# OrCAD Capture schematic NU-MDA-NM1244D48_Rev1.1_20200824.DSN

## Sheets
1 Connect: size A4; title: Nu-MDA-NM1244D48_Connect; rev: V1.0
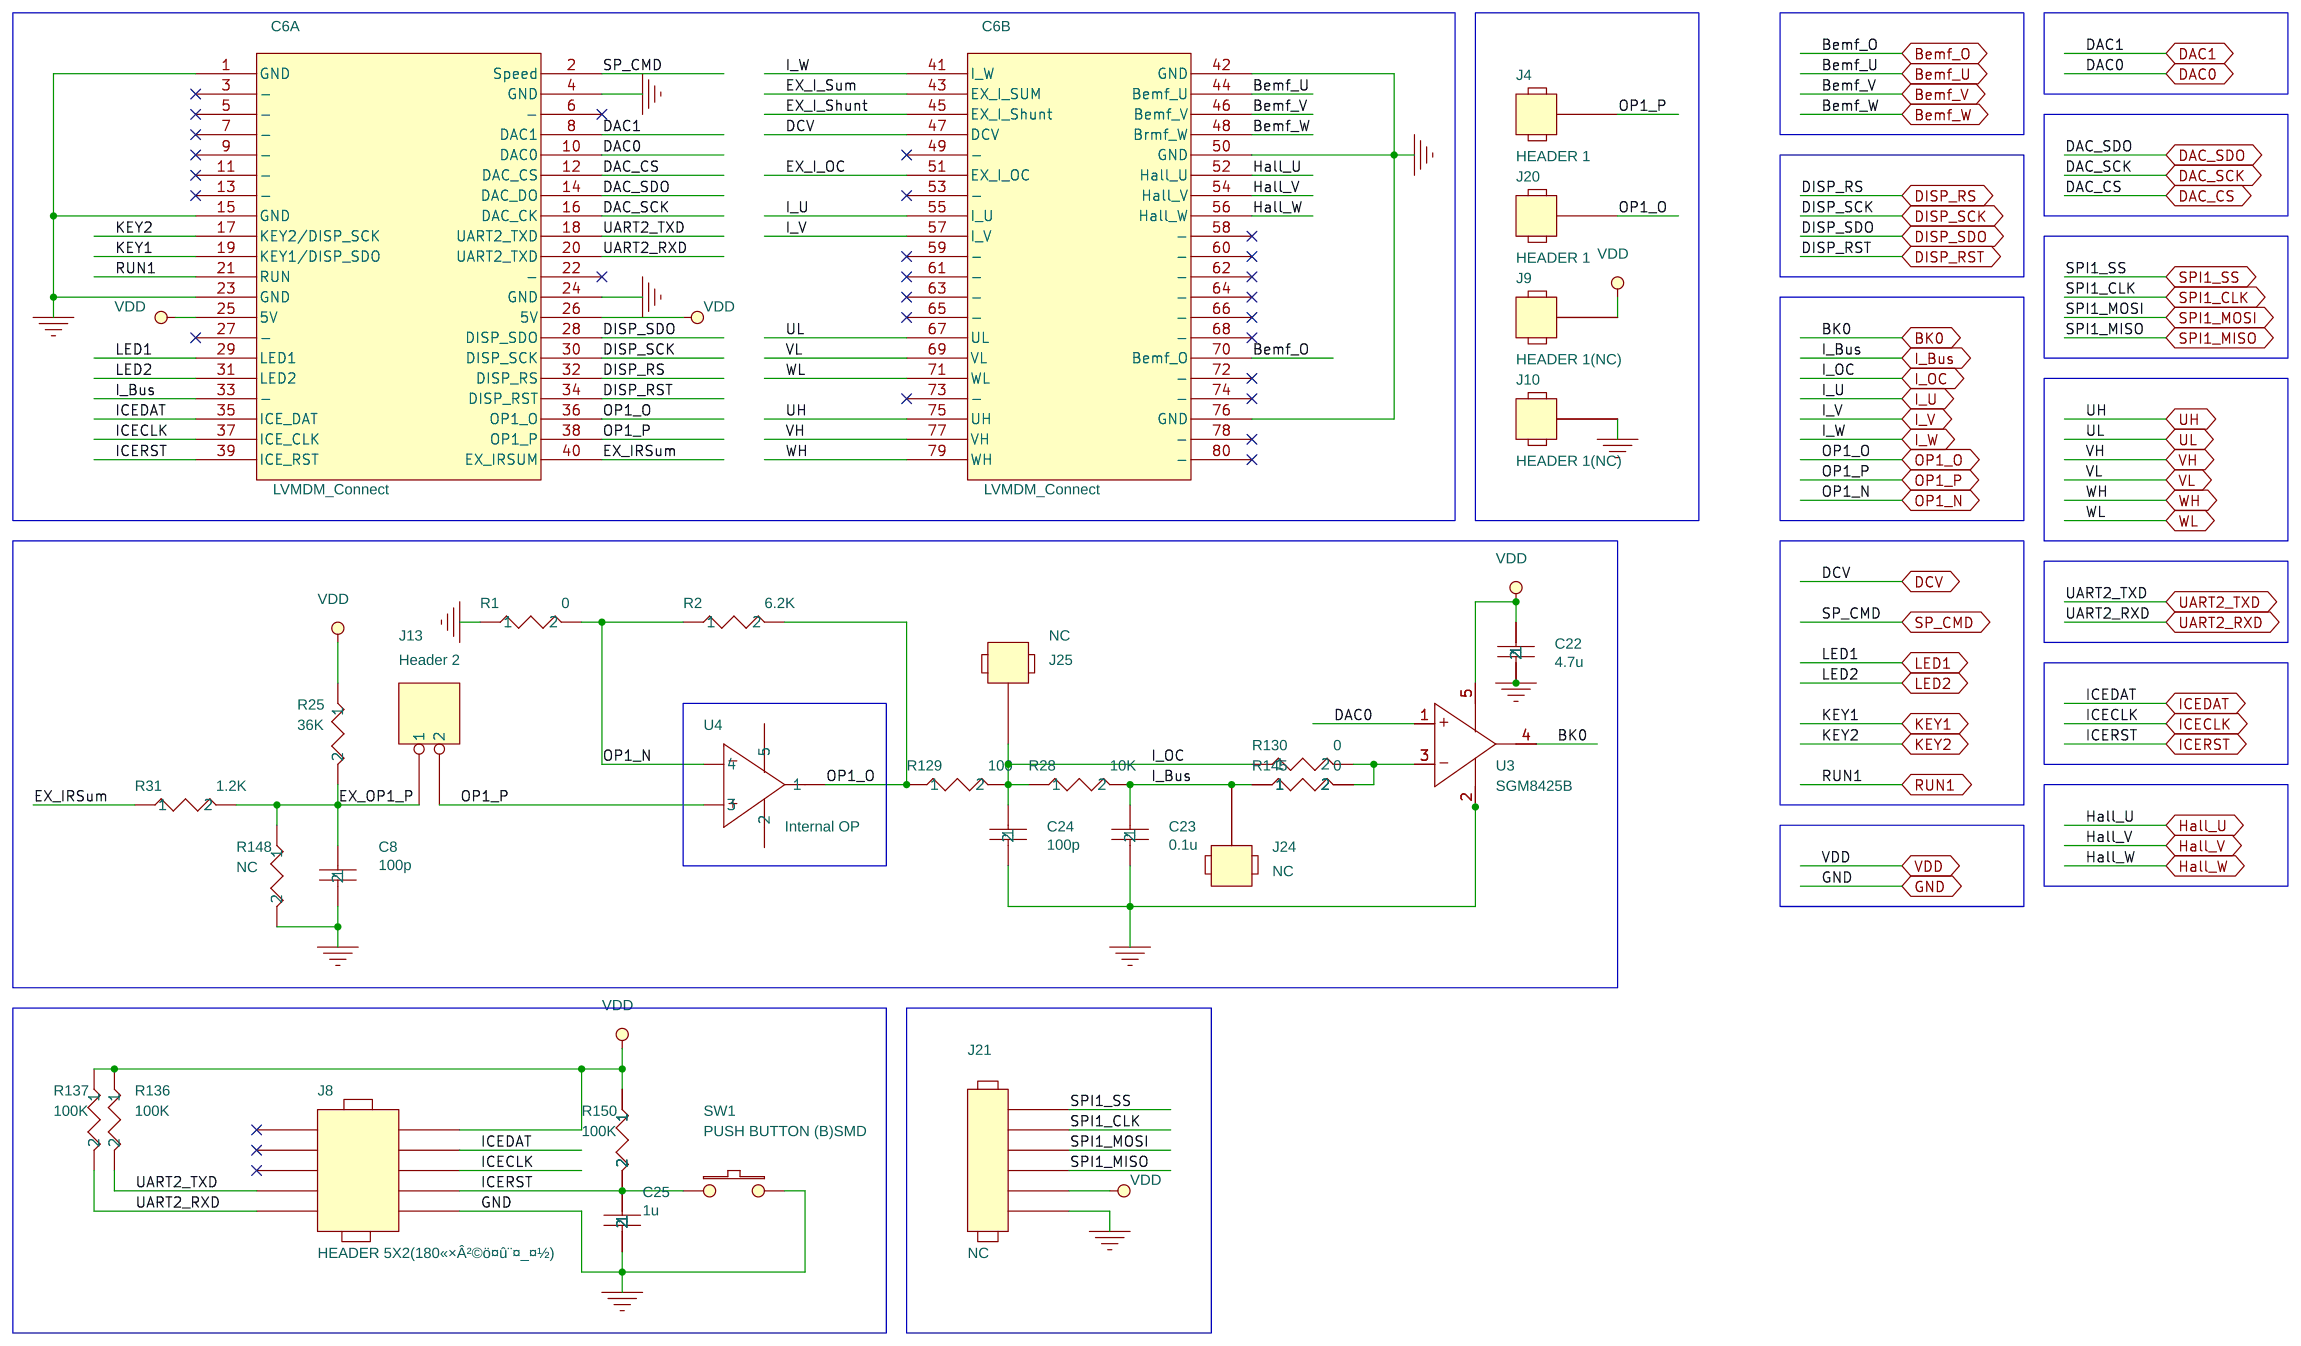
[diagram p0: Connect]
2 NM1244D48: size A3; title: Nu-MDA-NM1244D48
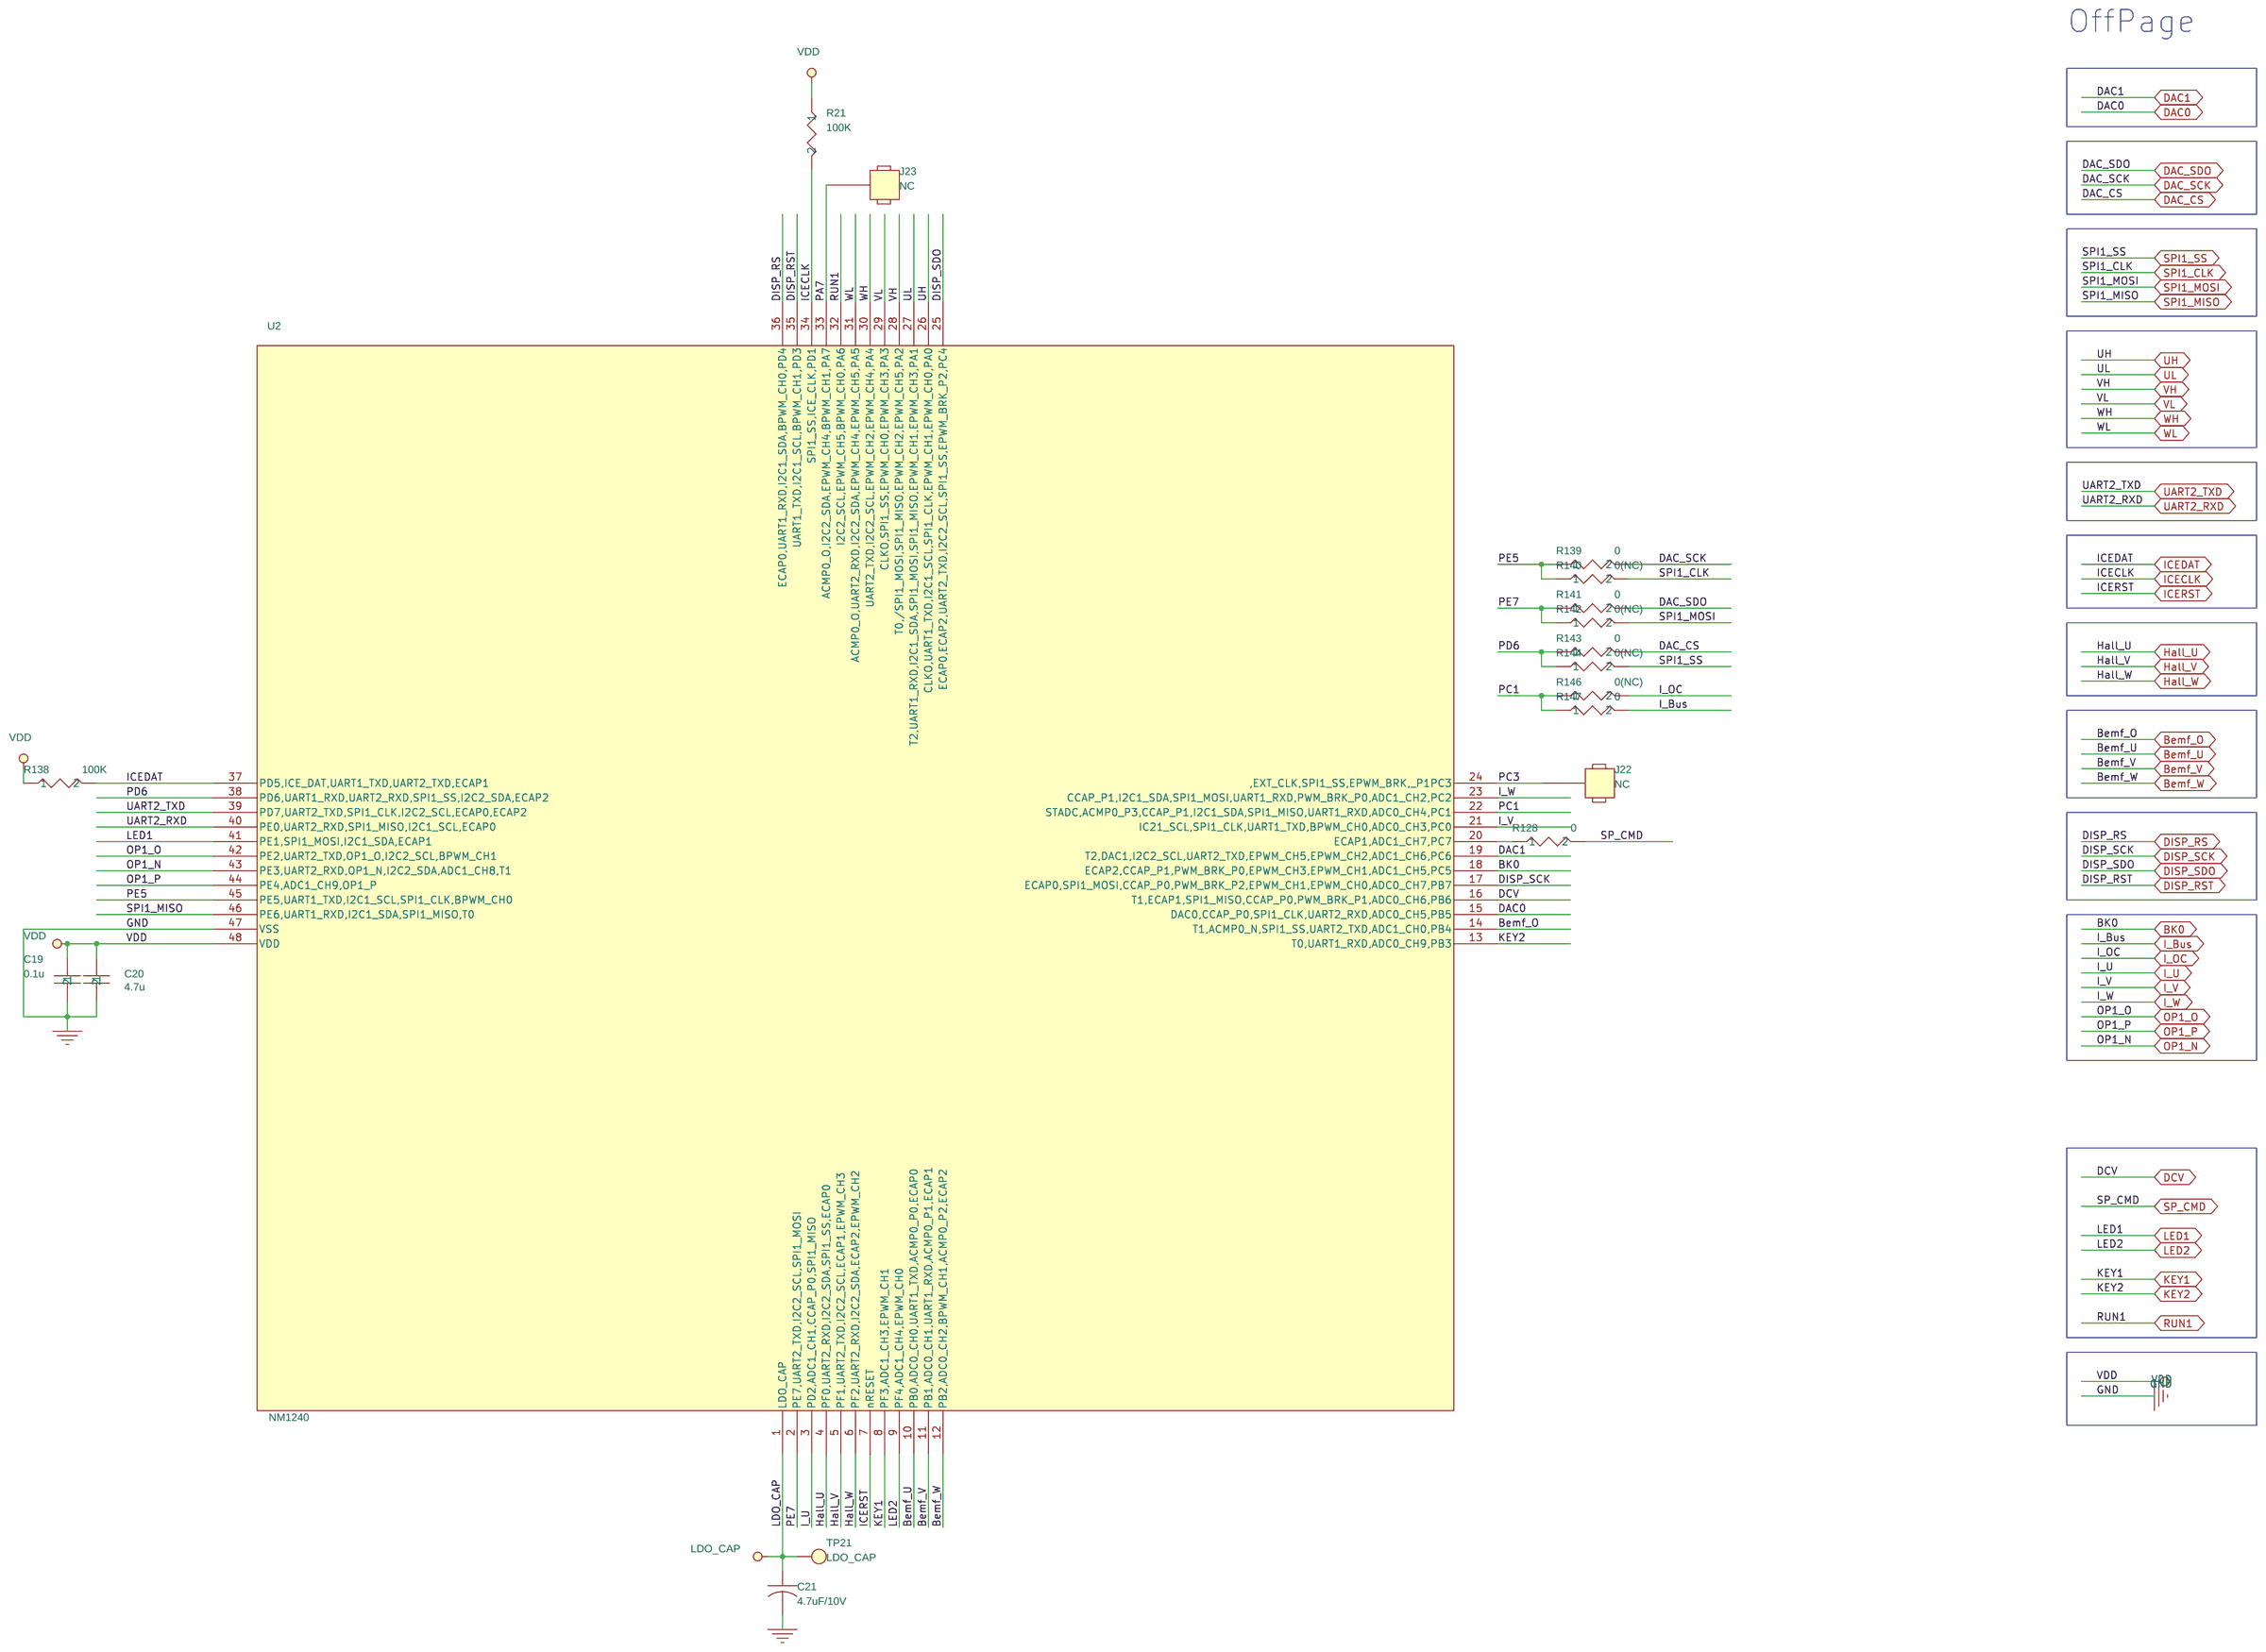
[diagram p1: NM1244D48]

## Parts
sheet Connect
C6  LVMDM_Connect  (sections A,B)
C8  100p  [C0603]
C22  4.7u  [C0603]
C23  0.1u  [C0603]
C24  100p  [C0603]
C25  1u  [C0603]
J4  HEADER 1  [sip-1p]
J8  HEADER 5X2(180«×Â²©ö¤û¨¤_¤½)  [header2x5]
J9  HEADER 1(NC)  [sip-1p]
J10  HEADER 1(NC)  [sip-1p]
J13  Header 2  [SIP-2P]
J20  HEADER 1  [sip-1p]
J21  NC
J24  NC  [sip-1p]
J25  NC  [sip-1p]
R1  0  [R0603]
R2  6.2K  [R0603]
R25  36K  [R0603]
R28  10K  [R0603]
R31  1.2K  [R0603]
R129  100  [R0603]
R130  0  [R0603]
R136  100K  [R0603]
R137  100K  [R0603]
R145  0  [R0603]
R148  NC  [R0603]
R150  100K  [R0603]
SW1  PUSH BUTTON (B)SMD  [SW_SMD_HSM]
U3  SGM8425B  [SOT-23-5]
U4  Internal OP
sheet NM1244D48
C19  0.1u  [C0603]
C20  4.7u  [C0603]
C21  4.7uF/10V  [TANT-A]
J22  NC  [sip-1p]
J23  NC  [sip-1p]
R21  100K  [R0603]
R128  0  [R0603]
R138  100K  [R0603]
R139  0  [R0603]
R140  0(NC)  [R0603]
R141  0  [R0603]
R142  0(NC)  [R0603]
R143  0  [R0603]
R144  0(NC)  [R0603]
R146  0(NC)  [R0603]
R147  0  [R0603]
TP21  LDO_CAP  [TEST_POINT_2MM_SMD]
U2  NM1240  [LQFP-48]

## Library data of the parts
C6 = LVMDM_Connect_7
C8 = C_1u_1
C22 = C_1u_3
C20 C23 = C_1u
C24 = C_1u_2
C25 = C_1u_4
J4 J9 J10 J20 J22-J25 = HEADER_1
J8 = HEADER_5X2
J13 = Header_0_ohm
J21 = HEADER_6
R1 R146 = R_1K_2
R2 R147 = R_1K_1
R25 = R_10K_1
R28 R128 = R_1K
R31 R144 = R_1K_5
R129 R140 = R_1K_3
R130 R139 = R_1K_6
R136 = R_10K_3
R137 = R_10K_4
R142 R145 = R_1K_4
R148 = R_10K
R150 = R_10K_2
SW1 = PUSH_BOTTOM_(B)
U3 = SGM8425B
U4 = SGM8631
C19 = C_0.1u
C21 = C_1uF_16V
R21 = R_100K_1
R138 = R_100K
R141 = R_1K_7
R143 = R_1K_8
TP21 = T_POINT_R
U2 = TF5103_3

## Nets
GND: C6.1(GND) C6.4(GND) C6.15(GND) C6.23(GND) C6.24(GND) C6.42(GND) C6.50(GND) C6.76(GND) C8.2 C19.2 C20.2 C21.2 C22.2 C23.2 C24.2 C25.2 J8.10 J10.1 J21.6 R1.1 R148.2 SW1.2 U2.47(VSS) U3.2
VDD: C6.25(5V) C6.26(5V) C19.1 C20.1 C22.1 J8.2 J9.1 J21.5 R21.1 R25.1 R136.1 R137.1 R138.1 R150.1 U2.48(VDD) U3.5
Bemf_O: C6.70(Bemf_O) U2.14(T1,ACMP0_N,SPI1_SS,UART2_TXD,ADC1_CH0,PB4)
Bemf_U: C6.44(Bemf_U) U2.10(PB0,ADC0_CH0,UART1_TXD,ACMP0_P0,ECAP0)
Bemf_V: C6.46(Bemf_V) U2.11(PB1,ADC0_CH1,UART1_RXD,ACMP0_P1,ECAP1)
Bemf_W: C6.48(Brmf_W) U2.12(PB2,ADC0_CH2,BPWM_CH1,ACMP0_P2,ECAP2)
BK0: U2.18(ECAP2,CCAP_P1,PWM_BRK_P0,EPWM_CH3,EPWM_CH1,ADC1_CH5,PC5) U3.4
DAC0: C6.10(DAC0) U2.15(DAC0,CCAP_P0,SPI1_CLK,UART2_RXD,ADC0_CH5,PB5) U3.1
DAC1: C6.8(DAC1) U2.19(T2,DAC1,I2C2_SCL,UART2_TXD,EPWM_CH5,EPWM_CH2,ADC1_CH6,PC6)
DAC_CS: C6.12(DAC_CS) R143.2
DAC_SCK: C6.16(DAC_CK) R139.2
DAC_SDO: C6.14(DAC_DO) R141.2
DCV: C6.47(DCV) U2.16(T1,ECAP1,SPI1_MISO,CCAP_P0,PWM_BRK_P1,ADC0_CH6,PB6)
DISP_RS: C6.32(DISP_RS) U2.36(ECAP0,UART1_RXD,I2C1_SDA,BPWM_CH0,PD4)
DISP_RST: C6.34(DISP_RST) U2.35(UART1_TXD,I2C1_SCL,BPWM_CH1,PD3)
DISP_SCK: C6.30(DISP_SCK) U2.17(ECAP0,SPI1_MOSI,CCAP_P0,PWM_BRK_P2,EPWM_CH1,EPWM_CH0,ADC0_CH7,PB7)
DISP_SDO: C6.28(DISP_SDO) U2.25(ECAP0,ECAP2,UART2_TXD,I2C2_SCL,SPI1_SS,EPWM_BRK_P2,PC4)
EX_I_OC: C6.51(EX_I_OC)
EX_I_Shunt: C6.45(EX_I_Shunt)
EX_I_Sum: C6.43(EX_I_SUM)
EX_IRSum: C6.40(EX_IRSUM) R31.1
EX_OP1_P: C8.1 J13.1 R25.2 R31.2 R148.1
Hall_U: C6.52(Hall_U) U2.4(PF0,UART2_RXD,I2C2_SDA,SPI1_SS,ECAP0)
Hall_V: C6.54(Hall_V) U2.5(PF1,UART2_TXD,I2C2_SCL,ECAP1,EPWM_CH3)
Hall_W: C6.56(Hall_W) U2.6(PF2,UART2_RXD,I2C2_SDA,ECAP2,EPWM_CH2)
I_Bus: C6.33(-) C23.1 J24.1 R28.2 R145.1 R147.2
I_OC: C24.1 J25.1 R28.1 R129.2 R130.1 R146.2
I_U: C6.55(I_U) U2.3(PD2,ADC1_CH1,CCAP_P0,SPI1_MISO)
I_V: C6.57(I_V) U2.21(IC21_SCL,SPI1_CLK,UART1_TXD,BPWM_CH0,ADC0_CH3,PC0)
I_W: C6.41(I_W) U2.23(CCAP_P1,I2C1_SDA,SPI1_MOSI,UART1_RXD,PWM_BRK_P0,ADC1_CH2,PC2)
ICECLK: C6.37(ICE_CLK) J8.6 R21.2 U2.34(SPI1_SS,ICE_CLK,PD1)
ICEDAT: C6.35(ICE_DAT) J8.4 R138.2 U2.37(PD5,ICE_DAT,UART1_TXD,UART2_TXD,ECAP1)
ICERST: C6.39(ICE_RST) C25.1 J8.8 R150.2 SW1.1 U2.7(nRESET)
KEY1: C6.19(KEY1/DISP_SDO) U2.8(PF3,ADC1_CH3,EPWM_CH1)
KEY2: C6.17(KEY2/DISP_SCK) U2.13(T0,UART1_RXD,ADC0_CH9,PB3)
LDO_CAP: C21.1 TP21.1(TP) U2.1(LDO_CAP)
LED1: C6.29(LED1) U2.41(PE1,SPI1_MOSI,I2C1_SDA,ECAP1)
LED2: C6.31(LED2) U2.9(PF4,ADC1_CH4,EPWM_CH0)
OP1_N: R1.2 R2.1 U2.43(PE3,UART2_RXD,OP1_N,I2C2_SDA,ADC1_CH8,T1) U4.4
OP1_O: C6.36(OP1_O) J20.1 R2.2 R129.1 U2.42(PE2,UART2_TXD,OP1_O,I2C2_SCL,BPWM_CH1) U4.1
OP1_P: C6.38(OP1_P) J4.1 J13.2 U2.44(PE4,ADC1_CH9,OP1_P) U4.3
PA7: J23.1 U2.33(ACMP0_O,I2C2_SDA,EPWM_CH4,BPWM_CH1,PA7)
PC1: R146.1 R147.1 U2.22(STADC,ACMP0_P3,CCAP_P1,I2C1_SDA,SPI1_MISO,UART1_RXD,ADC0_CH4,PC1)
PC3: J22.1 U2.24(,EXT_CLK,SPI1_SS,EPWM_BRK,_P1PC3)
PD6: R143.1 R144.1 U2.38(PD6,UART1_RXD,UART2_RXD,SPI1_SS,I2C2_SDA,ECAP2)
PE5: R139.1 R140.1 U2.45(PE5,UART1_TXD,I2C1_SCL,SPI1_CLK,BPWM_CH0)
PE7: R141.1 R142.1 U2.2(PE7,UART2_TXD,I2C2_SCL,SPI1_MOSI)
RUN1: C6.21(RUN) U2.32(I2C2_SCL,EPWM_CH5,BPWM_CH0,PA6)
SP_CMD: C6.2(Speed) R128.2
SPI1_CLK: J21.2 R140.2
SPI1_MISO: J21.4 U2.46(PE6,UART1_RXD,I2C1_SDA,SPI1_MISO,T0)
SPI1_MOSI: J21.3 R142.2
SPI1_SS: J21.1 R144.2
UART2_RXD: C6.20(UART2_TXD) J8.9 R137.2 U2.40(PE0,UART2_RXD,SPI1_MISO,I2C1_SCL,ECAP0)
UART2_TXD: C6.18(UART2_TXD) J8.7 R136.2 U2.39(PD7,UART2_TXD,SPI1_CLK,I2C2_SCL,ECAP0,ECAP2)
UH: C6.75(UH) U2.26(CLKO,UART1_TXD,I2C1_SCL,SPI1_CLK,EPWM_CH1,EPWM_CH0,PA0)
UL: C6.67(UL) U2.27(T2,UART1_RXD,I2C1_SDA,SPI1_MOSI,SPI1_MISO,EPWM_CH1,EPWM_CH3,PA1)
VH: C6.77(VH) U2.28(T0,/SPI1_MOSI,SPI1_MISO,EPWM_CH2,EPWM_CH5,PA2)
VL: C6.69(VL) U2.29(CLKO,SPI1_SS,EPWM_CH0,EPWM_CH3,PA3)
WH: C6.79(WH) U2.30(UART2_TXD,I2C2_SCL,EPWM_CH2,EPWM_CH4,PA4)
WL: C6.71(WL) U2.31(ACMP0_O,UART2_RXD,I2C2_SDA,EPWM_CH4,EPWM_CH5,PA5)
N211698: R130.2 R145.2 U3.3
N234237: R128.1 U2.20(ECAP1,ADC1_CH7,PC7)

Not connected (* = marked no-connect by the designer): C6 3(-)* 5(-)* 6(-)* 7(-)* 9(-)* 11(-)* 13(-)* 22(-)* 27(-)* 49(-)* 53(-)* 58(-)* 59(-)* 60(-)* 61(-)* 62(-)* 63(-)* 64(-)* 65(-)* 66(-)* 68(-)* 72(-)* 73(-)* 74(-)* 78(-)* 80(-)*; J8 1* 3* 5*; U4 2 5

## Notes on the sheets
sheet 2
- OffPage
